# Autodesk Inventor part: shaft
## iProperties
Created: 2008-06
Part Number: shaft
Document SubType Name: Modeling
Designer: CADCIM
Density: 1 g/cm^3
Author: CADCIM
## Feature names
1. Extrusion1
2. Chamfer1
3. Revolution1
